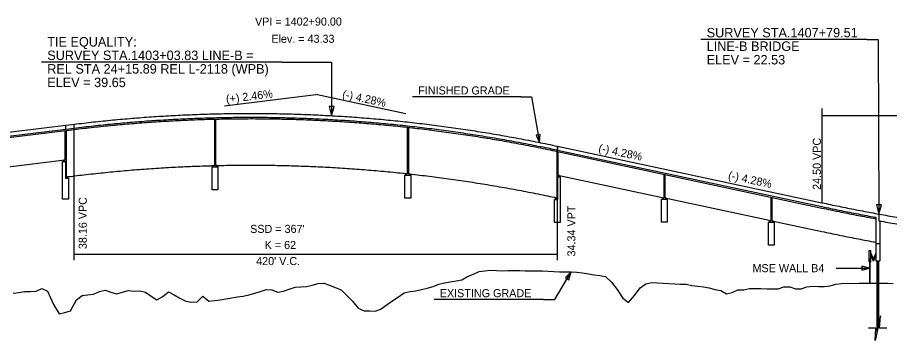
# Model space of a CAD drawing. Extents: x 2360994 to 2383826, y 330623 to 403123.
# Drawn here: x 2369756 to 2370514, y 346875 to 347157 of the extents above; entities that cross this region are included whole.
import ezdxf

# ---------------------------------------------------------------- set-up
doc = ezdxf.new("R2010")
doc.units = 0
for name, color, linetype in [('BR_DETAILS', 7, 'Continuous'), ('BR_STRUCTURAL STEEL', 7, 'Continuous'), ('RD_DDB_GradeTX', 7, 'Continuous'), ('RD_DDB_Profile_EX', 7, 'Continuous'), ('RD_DDB_Profile_Lbl', 7, 'Continuous'), ('RD_DDB_Profile_PR', 7, 'Continuous'), ('RD_DDB_StripGrade', 7, 'Continuous'), ('RD_DDB_VCLbl', 7, 'Continuous'), ('RD_PD_MedBWall', 7, 'Continuous'), ('RD_TX_Profile', 7, 'Continuous'), ('RD_XS_Bridge', 7, 'Continuous')]:
    doc.layers.add(name, color=color, linetype=linetype)

msp = doc.modelspace()

# ---------------------------------------------------------------- linework, layer by layer
at = {"layer": 'BR_DETAILS'}
for p, q in [((2370506.35, 346896.9), (2370501.74, 346875.45)), ((2370505.69, 346886.12), (2370506.35, 346896.9)), ((2370502.39, 346886.12), (2370496.04, 346886.12)), ((2370501.74, 346875.45), (2370502.39, 346886.12)), ((2370512.04, 346886.12), (2370505.69, 346886.12))]:
    msp.add_line(p, q, dxfattribs=at)
at = {"layer": 'BR_STRUCTURAL STEEL'}
for p, q in [((2370503.21, 346944.78), (2370503.21, 346882.27)), ((2370503.94, 346944.78), (2370503.94, 346885.7)), ((2370504.04, 346944.78), (2370504.04, 346886.17)), ((2370504.78, 346944.78), (2370504.78, 346889.61))]:
    msp.add_line(p, q, dxfattribs=at)
at = {"layer": 'RD_DDB_GradeTX'}
for p in [(2369936.16, 347079.75), (2370093.8, 347072.78)]:
    msp.add_line(p, (2370015.57, 347089.52), dxfattribs=at)
at = {"layer": 'RD_DDB_Profile_EX'}
for points in [[(2369842.54, 346916.11), (2369847.54, 346917.46), (2369852.54, 346918.95), (2369857.54, 346918.52), (2369862.54, 346918.73), (2369867.54, 346917.56), (2369872.54, 346914.01), (2369877.54, 346911.03), (2369882.54, 346913.76), (2369887.54, 346917.88), (2369892.54, 346915.12), (2369897.54, 346912.35), (2369902.54, 346909.66), (2369907.54, 346908.83), (2369912.54, 346909.27), (2369917.54, 346913.96), (2369922.54, 346909.83), (2369927.54, 346910.41), (2369932.54, 346911.02), (2369937.54, 346911.65), (2369942.54, 346912.62), (2369947.54, 346913.64), (2369952.54, 346914.23), (2369957.54, 346915.14), (2369962.54, 346916.66), (2369967.54, 346918.2), (2369972.54, 346919.75), (2369977.54, 346919.54), (2369982.54, 346917.65), (2369987.54, 346918.46), (2369992.54, 346920.26), (2369997.54, 346921.79), (2370002.54, 346922.12), (2370007.54, 346922.45), (2370012.54, 346923.56), (2370017.54, 346925.22), (2370022.54, 346925.54), (2370027.54, 346923.54), (2370032.54, 346921.54), (2370037.54, 346919.64), (2370042.54, 346914.71), (2370047.54, 346909.72), (2370052.54, 346903.61), (2370057.54, 346901.31), (2370062.54, 346901.23), (2370067.54, 346901.15), (2370072.54, 346903.01), (2370077.54, 346906.81), (2370082.54, 346910.37), (2370087.54, 346913.46), (2370092.54, 346917.13), (2370097.54, 346918.17), (2370102.54, 346918.86), (2370107.54, 346919.97), (2370112.54, 346921.01), (2370117.54, 346922.46), (2370122.54, 346924.42), (2370127.54, 346925.75), (2370132.54, 346926.43), (2370137.54, 346927.35), (2370142.54, 346928.42), (2370147.54, 346931.32), (2370152.54, 346933.21), (2370157.54, 346935.48), (2370162.54, 346935.99), (2370167.54, 346936.61), (2370172.54, 346936.53), (2370177.54, 346936.07), (2370182.54, 346936.45), (2370187.54, 346936.39), (2370192.54, 346936.32), (2370197.54, 346936.26), (2370202.54, 346936.2), (2370207.54, 346936.14), (2370212.54, 346936.04), (2370217.54, 346935.81), (2370222.54, 346935.58), (2370227.54, 346935.34), (2370232.54, 346935.25), (2370237.54, 346935.16), (2370242.54, 346935.06), (2370247.54, 346934.28), (2370252.54, 346933.43), (2370257.54, 346932.57), (2370262.54, 346932.15), (2370267.54, 346931.23), (2370272.54, 346926.32), (2370277.54, 346919.76), (2370282.54, 346912.22), (2370287.54, 346908.45), (2370292.54, 346914.63), (2370297.54, 346921.22), (2370302.54, 346924.73), (2370307.54, 346925.99), (2370312.54, 346925.73), (2370317.54, 346925.37), (2370322.54, 346924.97), (2370327.54, 346924.78), (2370332.54, 346924.54), (2370337.54, 346924.47), (2370342.54, 346923.45)], [(2369752.54, 346916.83), (2369757.54, 346917.31), (2369762.54, 346918.14), (2369767.54, 346918.24), (2369772.54, 346918.42), (2369777.54, 346920.82), (2369782.54, 346918.3), (2369787.54, 346906.95), (2369792.54, 346898.71), (2369797.54, 346899.99), (2369802.54, 346901.28), (2369807.54, 346910.88), (2369812.54, 346914.64), (2369817.54, 346915.29), (2369822.54, 346915.95), (2369827.54, 346918.23), (2369832.54, 346919.31), (2369837.54, 346917.7), (2369842.54, 346916.11)], [(2370342.54, 346923.45), (2370347.54, 346922.74), (2370352.54, 346922.33), (2370357.54, 346921.25), (2370362.54, 346919.84), (2370367.54, 346918.98), (2370372.54, 346916.26), (2370377.54, 346917.38), (2370382.54, 346919.73), (2370387.54, 346919.46), (2370392.54, 346920.67), (2370397.54, 346920.75), (2370402.54, 346920.63), (2370407.54, 346920.39), (2370412.54, 346920.38), (2370417.54, 346920.38), (2370422.54, 346922.21), (2370427.54, 346922.23), (2370432.54, 346920.34), (2370437.54, 346920.41), (2370442.54, 346922.19), (2370447.54, 346922.92), (2370452.54, 346922.56), (2370457.54, 346922.48), (2370462.54, 346923.13), (2370467.54, 346924.6), (2370472.54, 346925), (2370477.54, 346925.38), (2370482.54, 346925.18), (2370487.54, 346925.31), (2370492.54, 346925.38), (2370497.54, 346925.38), (2370502.54, 346925.38), (2370507.54, 346925.37), (2370512.54, 346925.33), (2370517.54, 346925.21)]]:
    msp.add_lwpolyline(points, dxfattribs=at)
at = {"layer": 'RD_DDB_Profile_PR'}
for p, q in [((2369587.57, 347036.89), (2369805.57, 347063.69)), ((2369587.57, 347036.89), (2369805.57, 347063.69)), ((2370225.56, 347044.58), (2370455.57, 346995.36)), ((2370225.56, 347044.58), (2370455.57, 346995.36))]:
    msp.add_line(p, q, dxfattribs=at)
for points in [[(2369805.57, 347063.69), (2369813.97, 347064.7), (2369822.37, 347065.65), (2369830.77, 347066.54), (2369839.17, 347067.37), (2369847.57, 347068.15), (2369855.97, 347068.87), (2369864.37, 347069.54), (2369872.77, 347070.15), (2369881.17, 347070.7), (2369889.57, 347071.19), (2369897.97, 347071.63), (2369906.37, 347072.01), (2369914.77, 347072.34), (2369923.17, 347072.61), (2369931.57, 347072.82), (2369939.97, 347072.98), (2369948.37, 347073.07), (2369956.77, 347073.12), (2369965.17, 347073.1), (2369973.57, 347073.03), (2369981.97, 347072.9), (2369990.37, 347072.72), (2369998.77, 347072.48), (2370007.17, 347072.18), (2370015.57, 347071.83), (2370023.97, 347071.42), (2370032.37, 347070.95), (2370040.77, 347070.43), (2370049.17, 347069.85), (2370057.57, 347069.21), (2370065.97, 347068.51), (2370074.37, 347067.76), (2370082.77, 347066.96), (2370091.17, 347066.09), (2370099.57, 347065.17), (2370107.97, 347064.2), (2370116.37, 347063.16), (2370124.77, 347062.07), (2370133.17, 347060.93), (2370141.57, 347059.72), (2370149.97, 347058.46), (2370158.37, 347057.15), (2370166.77, 347055.77), (2370175.16, 347054.35), (2370183.56, 347052.86), (2370191.96, 347051.32), (2370200.36, 347049.72), (2370208.76, 347048.06), (2370217.16, 347046.35), (2370225.56, 347044.58)], [(2369805.57, 347063.69), (2369813.97, 347064.7), (2369822.37, 347065.65), (2369830.77, 347066.54), (2369839.17, 347067.37), (2369847.57, 347068.15), (2369855.97, 347068.87), (2369864.37, 347069.54), (2369872.77, 347070.15), (2369881.17, 347070.7), (2369889.57, 347071.19), (2369897.97, 347071.63), (2369906.37, 347072.01), (2369914.77, 347072.34), (2369923.17, 347072.61), (2369931.57, 347072.82), (2369939.97, 347072.98), (2369948.37, 347073.07), (2369956.77, 347073.12), (2369965.17, 347073.1), (2369973.57, 347073.03), (2369981.97, 347072.9), (2369990.37, 347072.72), (2369998.77, 347072.48), (2370007.17, 347072.18), (2370015.57, 347071.83), (2370023.97, 347071.42), (2370032.37, 347070.95), (2370040.77, 347070.43), (2370049.17, 347069.85), (2370057.57, 347069.21), (2370065.97, 347068.51), (2370074.37, 347067.76), (2370082.77, 347066.96), (2370091.17, 347066.09), (2370099.57, 347065.17), (2370107.97, 347064.2), (2370116.37, 347063.16), (2370124.77, 347062.07), (2370133.17, 347060.93), (2370141.57, 347059.72), (2370149.97, 347058.46), (2370158.37, 347057.15), (2370166.77, 347055.77), (2370175.16, 347054.35), (2370183.56, 347052.86), (2370191.96, 347051.32), (2370200.36, 347049.72), (2370208.76, 347048.06), (2370217.16, 347046.35), (2370225.56, 347044.58)], [(2370455.57, 346995.36), (2370462.97, 346993.79), (2370470.37, 346992.26), (2370477.77, 346990.76), (2370485.17, 346989.3), (2370492.57, 346987.87), (2370499.97, 346986.47), (2370507.37, 346985.11), (2370514.77, 346983.78), (2370522.17, 346982.49), (2370529.57, 346981.23), (2370536.97, 346980), (2370544.37, 346978.81), (2370551.77, 346977.65), (2370559.17, 346976.53), (2370566.57, 346975.44), (2370573.97, 346974.38), (2370581.37, 346973.36), (2370588.77, 346972.38), (2370596.17, 346971.42), (2370603.57, 346970.5), (2370610.97, 346969.62), (2370618.37, 346968.77), (2370625.77, 346967.95), (2370633.17, 346967.17), (2370640.57, 346966.42), (2370647.97, 346965.71), (2370655.37, 346965.03), (2370662.77, 346964.38), (2370670.17, 346963.77), (2370677.57, 346963.19), (2370684.97, 346962.65), (2370692.37, 346962.14), (2370699.77, 346961.66), (2370707.17, 346961.22), (2370714.57, 346960.81), (2370721.97, 346960.44), (2370729.37, 346960.1), (2370736.77, 346959.79), (2370744.17, 346959.52), (2370751.57, 346959.28), (2370758.97, 346959.08), (2370766.37, 346958.91), (2370773.77, 346958.78), (2370781.17, 346958.67), (2370788.57, 346958.61), (2370795.97, 346958.57), (2370803.37, 346958.58), (2370810.77, 346958.61), (2370818.17, 346958.68), (2370825.57, 346958.78)]]:
    msp.add_spline(points, degree=3, dxfattribs=at)
at = {"layer": 'RD_DDB_VCLbl'}
for p, q in [((2370455.57, 347077.33), (2370455.57, 346995.36)), ((2370455.57, 347071.32), (2370825.57, 347071.32)), ((2369805.57, 346945.4), (2369805.57, 347063.69)), ((2370225.56, 346945.4), (2370225.56, 347044.58)), ((2369805.57, 346950.64), (2370225.56, 346950.64))]:
    msp.add_line(p, q, dxfattribs=at)
at = {"layer": 'RD_PD_MedBWall'}
for p, q in [((2370496.51, 346943.94), (2370496.51, 346953.94)), ((2370496.51, 346953.94), (2370498.01, 346953.94)), ((2370498.01, 346943.94), (2370498.01, 346953.94)), ((2370498.01, 346951.44), (2370500.01, 346946.44)), ((2370502.24, 346951.44), (2370500.24, 346946.44)), ((2370496.51, 346943.94), (2370497.01, 346943.94)), ((2370497.01, 346925.38), (2370497.01, 346946.44)), ((2370497.01, 346946.44), (2370497.51, 346946.44)), ((2370497.51, 346925.38), (2370497.51, 346946.44)), ((2370497.51, 346943.94), (2370498.01, 346943.94)), ((2370498.01, 346949.78), (2370500.01, 346944.78)), ((2370500.01, 346946.44), (2370500.24, 346946.44)), ((2370500.01, 346944.78), (2370500.24, 346944.78)), ((2370502.24, 346949.78), (2370500.24, 346944.78))]:
    msp.add_line(p, q, dxfattribs=at)
at = {"layer": 'RD_TX_Profile'}
for p, q in [((2370494.55, 347137.48), (2370350.33, 347137.48)), ((2369986.44, 347117.75), (2369777.21, 347117.75)), ((2370194.22, 347087.58), (2370099.65, 347087.58)), ((2370213.48, 346911.2), (2370118.36, 346911.2))]:
    msp.add_line(p, q, dxfattribs=at)
for points in [[(2370494.55, 347137.48), (2370504.5, 347137.48), (2370505.08, 346985.53)], [(2369986.44, 347117.75), (2370029.4, 347117.75), (2370029.4, 347071.12)], [(2370194.22, 347087.58), (2370203.21, 347087.58), (2370210.09, 347047.79)], [(2370467.78, 346938.45), (2370474.61, 346938.45), (2370496.96, 346938.45)], [(2370213.48, 346911.2), (2370223.4, 346911.2), (2370237.54, 346935.16)]]:
    msp.add_lwpolyline(points, dxfattribs=at)
for points in [[(2370027.27, 347079.08), (2370029.4, 347071.12), (2370031.53, 347079.08)], [(2370207.15, 347054.14), (2370210.09, 347047.79), (2370210.72, 347054.76)], [(2370502.92, 346993.47), (2370505.08, 346985.53), (2370507.18, 346993.49)], [(2370490.2, 346936.64), (2370496.96, 346938.45), (2370490.2, 346940.27)], [(2370235.66, 346928.41), (2370237.54, 346935.16), (2370232.54, 346930.25)]]:
    msp.add_lwpolyline(points, close=True, dxfattribs=at)
at = {"layer": 'RD_XS_Bridge'}
for p, q in [((2369927.58, 347068.16), (2369927.58, 347027.72)), ((2369928.58, 347068.16), (2369928.58, 347027.75)), ((2369587.57, 347033.55), (2369805.57, 347060.36)), ((2369587.57, 347032.3), (2369805.57, 347059.11)), ((2369797.58, 347058.19), (2369797.58, 347032.7)), ((2369798.08, 347062.77), (2369798.08, 347059.44)), ((2369798.58, 347058.19), (2369798.58, 347017.84)), ((2370095.08, 347061.03), (2370095.08, 347020.67)), ((2370096.08, 347061.03), (2370096.08, 347020.56)), ((2370225.56, 346992.08), (2370225.56, 347044.58)), ((2370225.58, 347044.58), (2370225.58, 347041.24)), ((2370225.08, 347039.99), (2370225.08, 346999.68)), ((2370225.56, 347041.25), (2370455.57, 346992.03)), ((2370225.56, 347040), (2370455.57, 346990.78)), ((2370226.08, 347039.99), (2370226.08, 347019.45)), ((2369686.58, 347019.05), (2369797.58, 347032.7)), ((2370226.08, 347019.45), (2370318.08, 346999.76)), ((2370318.08, 347020.09), (2370318.08, 346999.76)), ((2370319.08, 347020.09), (2370319.08, 346999.54)), ((2370319.08, 346999.54), (2370411.08, 346979.86)), ((2370411.08, 347000.19), (2370411.08, 346979.86)), ((2370412.08, 347000.19), (2370412.08, 346979.64)), ((2370502.24, 346982.72), (2370502.24, 346944.78)), ((2370505.08, 346985.53), (2370505.08, 346979.69)), ((2370412.08, 346979.64), (2370455.55, 346970.34)), ((2370505.74, 346979.57), (2370505.74, 346944.78)), ((2370502.24, 346959.78), (2370505.74, 346959.78)), ((2370502.24, 346944.78), (2370505.74, 346944.78))]:
    msp.add_line(p, q, dxfattribs=at)
for points in [[(2369795.58, 346998.51), (2369795.58, 347031.32)], [(2369795.58, 347031.32), (2369798.08, 347031.32)], [(2369798.08, 347031.32), (2369798.08, 347016.63)], [(2369798.08, 347016.63), (2369800.58, 347016.63)], [(2369800.58, 347016.63), (2369800.58, 346998.51)], [(2370225.58, 347017.96), (2370228.08, 347017.96)], [(2370225.58, 347017.96), (2370225.58, 346998.32)], [(2370228.08, 347017.96), (2370228.08, 346978.32)], [(2369800.58, 346998.51), (2369795.58, 346998.51)], [(2370223.08, 346978.32), (2370223.08, 346998.32)], [(2370223.08, 346998.32), (2370225.58, 346998.32)], [(2370228.08, 346978.32), (2370223.08, 346978.32)]]:
    msp.add_lwpolyline(points, dxfattribs=at)
for points in [[(2369797.08, 347031.32), (2369796.58, 347031.32), (2369796.58, 347032.57), (2369797.08, 347032.57)], [(2369925.58, 347006.48), (2369925.58, 347026.48), (2369930.58, 347026.48), (2369930.58, 347006.48)], [(2369927.08, 347026.48), (2369926.58, 347026.48), (2369926.58, 347027.74), (2369927.08, 347027.74)], [(2369929.08, 347026.48), (2369929.58, 347026.48), (2369929.58, 347027.74), (2369929.08, 347027.74)], [(2370093.08, 346999.36), (2370093.08, 347019.36), (2370098.08, 347019.36), (2370098.08, 346999.36)], [(2370094.58, 347019.36), (2370094.08, 347019.36), (2370094.08, 347020.62), (2370094.58, 347020.62)], [(2370096.58, 347019.36), (2370097.08, 347019.36), (2370097.08, 347020.62), (2370096.58, 347020.62)], [(2370226.58, 347018.02), (2370227.08, 347018.02), (2370227.08, 347019.28), (2370226.58, 347019.28)], [(2369799.25, 347016.63), (2369799.75, 347016.63), (2369799.75, 347017.89), (2369799.25, 347017.89)], [(2370224.58, 346998.32), (2370224.08, 346998.32), (2370224.08, 346999.58), (2370224.58, 346999.58)], [(2370316.08, 346978.4), (2370316.08, 346998.4), (2370321.08, 346998.4), (2370321.08, 346978.4)], [(2370317.58, 346998.4), (2370317.08, 346998.4), (2370317.08, 346999.66), (2370317.58, 346999.66)], [(2370319.58, 346998.4), (2370320.08, 346998.4), (2370320.08, 346999.66), (2370319.58, 346999.66)], [(2370409.08, 346958.5), (2370409.08, 346978.5), (2370414.08, 346978.5), (2370414.08, 346958.5)], [(2370410.58, 346978.5), (2370410.08, 346978.5), (2370410.08, 346979.76), (2370410.58, 346979.76)], [(2370412.58, 346978.5), (2370413.08, 346978.5), (2370413.08, 346979.76), (2370412.58, 346979.76)]]:
    msp.add_lwpolyline(points, close=True, dxfattribs=at)
for points in [[(2369805.57, 347060.36), (2369813.97, 347061.37), (2369822.37, 347062.31), (2369830.77, 347063.2), (2369839.17, 347064.04), (2369847.57, 347064.82), (2369855.97, 347065.54), (2369864.37, 347066.2), (2369872.77, 347066.81), (2369881.17, 347067.36), (2369889.57, 347067.86), (2369897.97, 347068.3), (2369906.37, 347068.68), (2369914.77, 347069.01), (2369923.17, 347069.27), (2369931.57, 347069.49), (2369939.97, 347069.64), (2369948.37, 347069.74), (2369956.77, 347069.78), (2369965.17, 347069.77), (2369973.57, 347069.7), (2369981.97, 347069.57), (2369990.37, 347069.39), (2369998.77, 347069.15), (2370007.17, 347068.85), (2370015.57, 347068.49), (2370023.97, 347068.08), (2370032.37, 347067.62), (2370040.77, 347067.09), (2370049.17, 347066.51), (2370057.57, 347065.87), (2370065.97, 347065.18), (2370074.37, 347064.43), (2370082.77, 347063.62), (2370091.17, 347062.76), (2370099.57, 347061.84), (2370107.97, 347060.86), (2370116.37, 347059.83), (2370124.77, 347058.74), (2370133.17, 347057.59), (2370141.57, 347056.39), (2370149.97, 347055.13), (2370158.37, 347053.81), (2370166.77, 347052.44), (2370175.16, 347051.01), (2370183.56, 347049.53), (2370191.96, 347047.98), (2370200.36, 347046.38), (2370208.76, 347044.73), (2370217.16, 347043.01), (2370225.56, 347041.25)], [(2369805.57, 347059.11), (2369813.97, 347060.12), (2369822.37, 347061.06), (2369830.77, 347061.95), (2369839.17, 347062.79), (2369847.57, 347063.57), (2369855.97, 347064.29), (2369864.37, 347064.95), (2369872.77, 347065.56), (2369881.17, 347066.11), (2369889.57, 347066.61), (2369897.97, 347067.05), (2369906.37, 347067.43), (2369914.77, 347067.76), (2369923.17, 347068.02), (2369931.57, 347068.24), (2369939.97, 347068.39), (2369948.37, 347068.49), (2369956.77, 347068.53), (2369965.17, 347068.52), (2369973.57, 347068.45), (2369981.97, 347068.32), (2369990.37, 347068.14), (2369998.77, 347067.9), (2370007.17, 347067.6), (2370015.57, 347067.24), (2370023.97, 347066.83), (2370032.37, 347066.37), (2370040.77, 347065.84), (2370049.17, 347065.26), (2370057.57, 347064.62), (2370065.97, 347063.93), (2370074.37, 347063.18), (2370082.77, 347062.37), (2370091.17, 347061.51), (2370099.57, 347060.59), (2370107.97, 347059.61), (2370116.37, 347058.58), (2370124.77, 347057.49), (2370133.17, 347056.34), (2370141.57, 347055.14), (2370149.97, 347053.88), (2370158.37, 347052.56), (2370166.77, 347051.19), (2370175.16, 347049.76), (2370183.56, 347048.28), (2370191.96, 347046.73), (2370200.36, 347045.13), (2370208.76, 347043.48), (2370217.16, 347041.76), (2370225.56, 347040)], [(2369798.58, 347017.84), (2369813.97, 347019.7), (2369822.37, 347020.64), (2369830.77, 347021.53), (2369839.17, 347022.37), (2369847.57, 347023.15), (2369855.97, 347023.87), (2369864.37, 347024.53), (2369872.77, 347025.14), (2369881.17, 347025.69), (2369889.57, 347026.19), (2369897.97, 347026.63), (2369906.37, 347027.01), (2369914.77, 347027.34), (2369923.17, 347027.6), (2369927.58, 347027.72)], [(2369928.58, 347027.75), (2369931.57, 347027.82), (2369939.97, 347027.97), (2369948.37, 347028.07), (2369956.77, 347028.11), (2369965.17, 347028.1), (2369973.57, 347028.03), (2369981.97, 347027.9), (2369990.37, 347027.72), (2369998.77, 347027.48), (2370007.17, 347027.18), (2370015.57, 347026.82), (2370023.97, 347026.41), (2370032.37, 347025.95), (2370040.77, 347025.42), (2370049.17, 347024.84), (2370057.57, 347024.2), (2370065.97, 347023.51), (2370074.37, 347022.76), (2370082.77, 347021.95), (2370091.17, 347021.09), (2370095.08, 347020.67)], [(2370096.08, 347020.56), (2370099.57, 347020.17), (2370107.97, 347019.19), (2370116.37, 347018.16), (2370124.77, 347017.07), (2370133.17, 347015.92), (2370141.57, 347014.72), (2370149.97, 347013.46), (2370158.37, 347012.14), (2370166.77, 347010.77), (2370175.16, 347009.34), (2370183.56, 347007.86), (2370191.96, 347006.31), (2370200.36, 347004.71), (2370208.76, 347003.06), (2370217.16, 347001.34), (2370225.08, 346999.68)], [(2370455.57, 346992.03), (2370462.97, 346990.46), (2370470.37, 346988.93), (2370477.77, 346987.43), (2370485.17, 346985.96), (2370492.57, 346984.53), (2370499.97, 346983.14), (2370502.24, 346982.72)], [(2370455.57, 346990.78), (2370462.97, 346989.21), (2370470.37, 346987.68), (2370477.77, 346986.18), (2370485.17, 346984.71), (2370492.57, 346983.28), (2370499.97, 346981.89), (2370502.24, 346981.47)], [(2370505.08, 346979.69), (2370507.37, 346979.28), (2370514.77, 346977.95), (2370522.17, 346976.65), (2370525.08, 346976.15)], [(2370455.57, 346970.34), (2370462.97, 346968.77), (2370470.37, 346967.24), (2370477.77, 346965.74), (2370485.17, 346964.27), (2370492.57, 346962.84), (2370499.97, 346961.45), (2370502.24, 346961.03)]]:
    msp.add_spline(points, degree=3, dxfattribs=at)

# ---------------------------------------------------------------- texts
at = {"layer": 'RD_DDB_GradeTX'}
for s, rotation, p in [('(+) 2.46%', 7.01061, (2369938.02, 347082)), ('(-) 4.28%', 347.92105, (2370038.19, 347086.72)), ('(-) 4.28%', 347.92105, (2370260.86, 347039.87)), ('(-) 4.28%', 347.92105, (2370373.54, 347016.14))]:
    msp.add_text(s, height=7, rotation=rotation, dxfattribs=at).set_placement(p)
at = {"layer": 'RD_DDB_Profile_Lbl'}
for s, p in [('VPI = 1402+90.00', (2369962.8, 347149.52)), ('Elev. = 43.33', (2369976.97, 347134.52))]:
    msp.add_text(s, height=7, dxfattribs=at).set_placement(p)
at = {"layer": 'RD_DDB_StripGrade'}
for s, p in [('24.50 VPC', (2370454.57, 347006.61)), ('38.16 VPC', (2369816.54, 346955.04)), ('34.34 VPT', (2370241.23, 346948.64))]:
    msp.add_text(s, height=7, rotation=90, dxfattribs=at).set_placement(p)
at = {"layer": 'RD_DDB_VCLbl'}
for s, p in [("SSD = 367'", (2369958.56, 346969.13)), ('K = 62', (2369971.15, 346955.13)), ("420' V.C.", (2369963.79, 346941.13))]:
    msp.add_text(s, height=7, dxfattribs=at).set_placement(p)
at = {"layer": 'RD_TX_Profile'}
for s, height, p in [('SURVEY STA.1407+79.51', 8.2353, (2370355.33, 347139.25)), ('TIE EQUALITY:', 8.2353, (2369782.21, 347131.28)), ('LINE-B BRIDGE', 8.2353, (2370355.33, 347127.48)), ('SURVEY STA.1403+03.83 LINE-B =', 8.2353, (2369782.21, 347119.52)), ('ELEV = 22.53', 8.2353, (2370355.33, 347115.72)), ('REL STA 24+15.89 REL L-2118 (WPB)', 8.2353, (2369782.21, 347107.75)), ('ELEV = 39.65', 8.2353, (2369782.21, 347095.99)), ('FINISHED GRADE', 7, (2370104.65, 347089.58)), ('MSE WALL B4', 7, (2370395.21, 346934.95)), ('EXISTING GRADE', 7, (2370123.36, 346913.2))]:
    msp.add_text(s, height=height, dxfattribs=at).set_placement(p)

doc.saveas('drawing.dxf')
